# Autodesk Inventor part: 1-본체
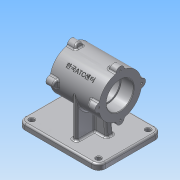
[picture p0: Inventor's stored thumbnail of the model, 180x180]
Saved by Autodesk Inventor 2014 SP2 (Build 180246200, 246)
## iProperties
Created: 2015-12
Part Number: 1-본체
Material: 알루미늄 6061
Document SubType Name: Modeling
Designer: Administrator
Density: 2.71 g/cm^3
Appearance: 알루미늄 - 평지
Mass: 1165.38 g
Surface Area: 815.069 cm^2
Volume: 430.029 cm^3
Author: Administrator
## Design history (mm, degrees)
sketch "스케치1"
  geometry: L1 (-80, 55)-(60, 55); L2 (60, 55)-(60, -55); L3 (60, -55)-(-80, -55); L4 (-80, -55)-(-80, 55); 2 further points
  constraints: 8 end point, 2 parallel, 1 horizontal, 1 horizontal alignment, 1 midpoint, 1 perpendicular
  dimensions: "d0" = 140 distance of L1.start L1.end; "d1" = 110 distance of L1.end L2.end; "d2" = 80 distance from line of point (0, 0) L4
extrude "돌출1" new body sketch "스케치1" distance "d3" = 10; taper "d4" = 0 deg
fillet "모깎기1" dims "d5" = 12
fillet "모깎기2" dims "d6" = 3
sketch "스케치2"
  geometry: A1 r 9 centre (48, -43) between (48, -52) and (57, -43) reference; A2 r 9 centre (48, 43) between (57, 43) and (48, 52) reference; A3 r 9 centre (-68, 43) between (-68, 52) and (-77, 43) reference; A4 r 9 centre (-68, -43) between (-77, -43) and (-68, -52) reference; 1 further point
hole "구멍1" sketch "스케치2" at (-68, -43), (48, -43), (48, 43), (-68, 43) diameter "d7" = 8; stored, may be unused: countersink angle "d11" = 90 deg, drill point angle "d13" = 118 deg; dims "d8" = 6, "d9" = 4, "d10" = 2, "d12" = 8
node "작업 평면1"
sketch "스케치3"
  geometry: L1 (0, 37)-(0, -37); 2 further points
  constraints: 2 end point, 1 coincident, 1 midpoint, 1 vertical
  dimensions: "d15" = 74 distance of L1.start L1.end
feature "리브1" sketch "스케치3" dims "d16" = 8, "d17" = 1, "d18" = 0, "d19" = 0, "d20" = 1, "d21" = 1
sketch "스케치4"
  geometry: L1 (-43, 0)-(43, 0) reference; C1 r 37 at (0, 80); 1 further point
  constraints: 1 centre point
  dimensions: "d22" = 80 distance from line of L1 C1.centre; "d23" = 74 diameter of C1
extrude "돌출2" join sketch "스케치4" stored distance "d24" = 85; taper "d25" = 0 deg
sketch "스케치5"
  geometry: L1 (80, 7)-(80, 0) reference; L2 (80, 0)-(-60, 0) reference; L3 (-60, 0)-(-60, 7) reference; L4 (-57, 10)-(-4, 10) reference; L5 (-4, 10)-(-4, 43) reference; L6 (-4, 43)-(-42.5, 43) reference; L7 (-42.5, 43)-(-42.5, 117) reference; L8 (-42.5, 117)-(42.5, 117) reference; L9 (42.5, 117)-(42.5, 43) reference; L10 (42.5, 43)-(4, 43) reference; L11 (4, 43)-(4, 10) reference; L12 (4, 10)-(77, 10) reference; L13 (-25, 10)-(-21.667, 37.148); L14 (0, 0)-(0, 47.319); A1 r 3 centre (77, 7) between (80, 7) and (77, 10) reference; A2 r 3 centre (-57, 7) between (-57, 10) and (-60, 7) reference
  constraints: 4 end point, 1 parallel, 1 point on line
  dimensions: "d26" = 25 horizontal distance of L14.start L13.start; "d27" = 97 deg angle of L13 L4; "d76" = 50 diameter of L13.start L14 (derived)
feature "리브2" sketch "스케치5" dims "d28" = 1, "d29" = 12, "d30" = 0, "d31" = 0, "d32" = 1, "d33" = 1
sketch "스케치6"
  geometry: C1 r 7 at (-37, 0); 2 further points
  constraints: 1 centre point, 1 horizontal alignment, 1 other
  dimensions: "d34" = 14 diameter of C1
extrude "돌출3" join sketch "스케치6" distance "d35" = 15; taper "d36" = 0 deg
sketch "스케치7"
  geometry: L1 (80, 0)-(-60, 0) reference; L2 (-60, 0)-(-60, 7) reference; L3 (-57, 10)-(-25, 10) reference; L4 (-25, 10)-(-20.948, 43) reference; L5 (-20.948, 43)-(-42.5, 43) reference; L6 (-42.5, 43)-(-42.5, 124) reference; L7 (-42.5, 124)-(-27.5, 124) reference; L8 (-27.5, 124)-(-27.5, 117) reference; L9 (-27.5, 117)-(42.5, 117) reference; L10 (42.5, 117)-(42.5, 43) reference; L11 (42.5, 43)-(20.948, 43) reference; L12 (20.948, 43)-(25, 10) reference; L13 (25, 10)-(77, 10) reference; L14 (80, 7)-(80, 0) reference; L15 (80, 0)-(-60, 0) reference; L16 (-60, 0)-(-60, 7) reference; L17 (-57, 10)-(-25, 10) reference; L18 (-25, 10)-(-20.948, 43) reference; L19 (-20.948, 43)-(-42.5, 43) reference; L20 (-42.5, 43)-(-42.5, 124) reference; L21 (-42.5, 124)-(-27.5, 124) reference; L22 (-27.5, 124)-(-27.5, 117) reference; L23 (-27.5, 117)-(42.5, 117) reference; L24 (42.5, 117)-(42.5, 43) reference; L25 (42.5, 43)-(20.948, 43) reference; L26 (20.948, 43)-(25, 10) reference; L27 (25, 10)-(77, 10) reference; L28 (80, 7)-(80, 0) reference; L29 (-27.5, 117)-(-30.048, 124); L30 (42.5, 80)-(-42.5, 80); A1 r 3 centre (-57, 7) between (-57, 10) and (-60, 7) reference; A2 r 3 centre (77, 7) between (80, 7) and (77, 10) reference; A3 r 3 centre (-57, 7) between (-57, 10) and (-60, 7) reference; A4 r 3 centre (77, 7) between (80, 7) and (77, 10) reference; 1 further point
  constraints: 4 end point, 2 point on line, 1 midpoint, 1 perpendicular
  dimensions: "d37" = 110 deg angle of L9 L29
revolve "회전1" sketch "스케치7" stored, may be unused: angle "d38" = 90 deg
sketch "스케치8"
  geometry: A1 r 7 centre (-117, 0) between (-116.338, 6.969) and (-116.338, -6.969) reference; 3 further points
hole "구멍2" sketch "스케치8" at (-117, 0) diameter "d41" = 3.242; stored, may be unused: countersink angle "d45" = 90 deg, drill point angle "d47" = 118 deg; dims "d42" = 9, "d43" = 4, "d44" = 2, "d46" = 11
fillet "모깎기8" dims "d74" = 3
fillet "모깎기9" dims "d75" = 3
fillet "모깎기5" dims "d51" = 3
fillet "모깎기6" dims "d52" = 3
sketch "스케치9"
  geometry: A1 r 37 centre (-80, 0) between (-44.138, 9.104) and (-70.896, 35.863) reference; 3 further points
hole "구멍3" sketch "스케치9" at (-80, 0) diameter "d53" = 42; stored, may be unused: countersink angle "d57" = 90 deg, drill point angle "d59" = 118 deg; dims "d54" = 9, "d55" = 47, "d56" = 22, "d58" = 11
chamfer "모따기1" distance "d60" = 1; stored, may be unused: second distance "d61" = 2, angle "d62" = 45 deg
fillet "모깎기7" dims "d63" = 0.3
sketch "스케치10"
  geometry: L1 (55, 0)-(-55, 0) reference; L2 (-55, 0)-(-55, 7) reference; L3 (-52, 10)-(-40, 10) reference; L4 (-37, 13)-(-37, 80) reference; L5 (37, 80)-(37, 13) reference; L6 (40, 10)-(52, 10) reference; L7 (55, 7)-(55, 0) reference; L8 (0, 80)-(-37, 80); L9 (0, 80)-(-30.979, 110.979); C1 r 21 at (0, 80) reference; A1 r 3 centre (-52, 7) between (-52, 10) and (-55, 7) reference; A2 r 3 centre (-40, 13) between (-40, 10) and (-37, 13) reference; A3 r 37 centre (0, 80) between (37, 80) and (-37, 80) reference; A4 r 3 centre (40, 13) between (37, 13) and (40, 10) reference; A5 r 3 centre (52, 7) between (55, 7) and (52, 10) reference; 1 further point
  constraints: 4 end point, 1 point on circle
  dimensions: "d64" = 45 deg angle of L8 L9
  node "절단 모서리 투영4"
node "작업 평면2"
sketch "스케치11"
  geometry: 7 further points; 1 other entity
  constraints: 1 coincident, 1 vertical alignment, 1 other
  dimensions: "d65" = 42.5 dimension on point (0, 0) (derived)
feature "엠보싱1" sketch "스케치11" dims "d0" = 140, "d1" = 110, "d2" = 80, "d66" = 0.5, "d67" = 0
chamfer "모따기2" distance "d68" = 1; stored, may be unused: second distance "d69" = 2, angle "d70" = 45 deg
node "솔리드1"
mirror "대칭1"
pattern_circular "원형 패턴2" dims "d72" = 360 deg
mirror "대칭4"
mirror "대칭3"
node "절단 모서리 투영1"
node "절단 모서리 투영2"
node "절단 모서리 투영3"
